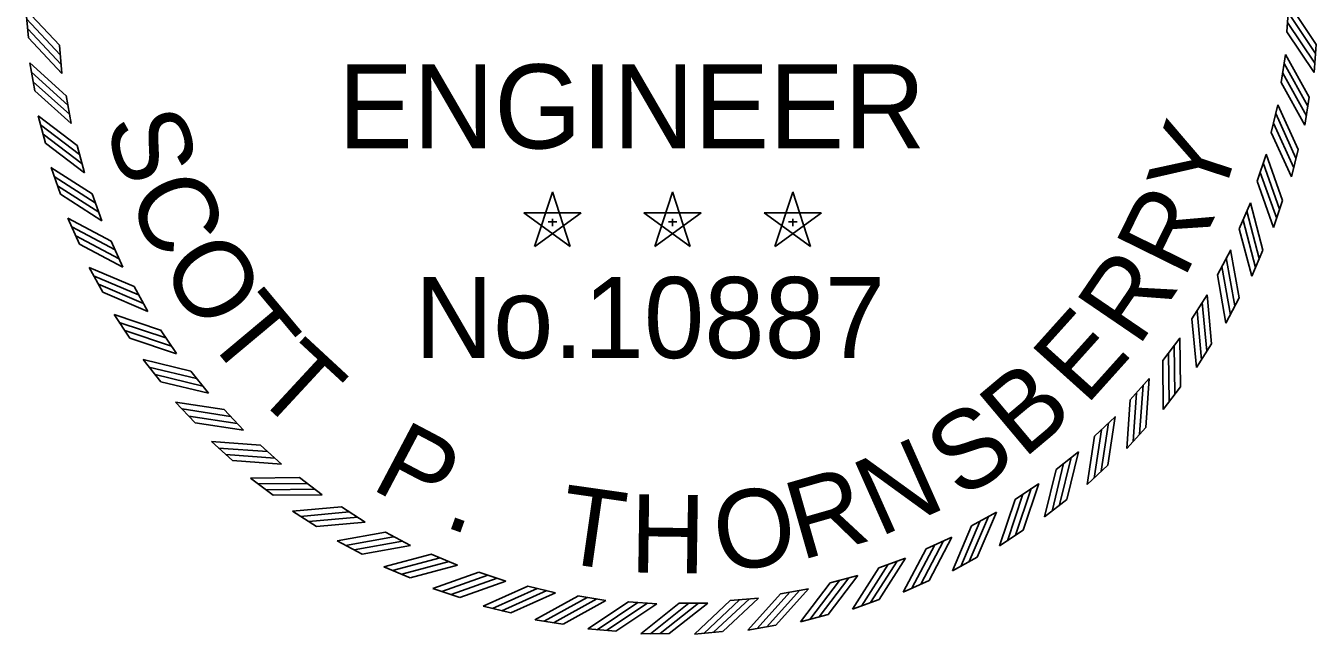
# Model space of a CAD drawing. Extents: x 3046 to 131673, y -8885 to 10756.
# Drawn here: x 3046.5 to 3294.3, y 323.2 to 440.1 of the extents above; entities that cross this region are included whole.
import ezdxf

# ---------------------------------------------------------------- set-up
doc = ezdxf.new("R2010")
doc.units = 0
doc.layers.add('STAMP_PP', color=7, linetype='Continuous')

msp = doc.modelspace()

# ---------------------------------------------------------------- linework, layer by layer
at = {"layer": 'STAMP_PP'}
for p, q in [((3289.08, 444.37), (3288.68, 438.93)), ((3046.98, 437.8), (3046.48, 443.22)), ((3053.43, 430.94), (3052.93, 436.37)), ((3294.31, 436.54), (3293.91, 431.11)), ((3288.42, 434.6), (3287.58, 429.21)), ((3048.2, 427.61), (3047.25, 432.97)), ((3055.19, 421.31), (3054.24, 426.68)), ((3292.99, 426.36), (3292.14, 420.99)), ((3286.96, 424.92), (3285.67, 419.62)), ((3050.25, 417.57), (3048.87, 422.83)), ((3057.74, 411.86), (3056.35, 417.13)), ((3284.71, 415.4), (3282.99, 410.22)), ((3290.83, 416.34), (3289.55, 411.05)), ((3053.13, 407.72), (3051.32, 412.85)), ((3061.06, 402.65), (3059.24, 407.79)), ((3147.61, 408.16), (3144.21, 397.72)), ((3151, 397.72), (3147.62, 408.17)), ((3170.69, 408.16), (3167.28, 397.72)), ((3174.08, 397.72), (3170.7, 408.17)), ((3193.77, 408.16), (3190.36, 397.72)), ((3197.16, 397.72), (3193.77, 408.17)), ((3287.86, 406.52), (3286.14, 401.36)), ((3153.1, 404.17), (3142.11, 404.19)), ((3142.12, 404.17), (3151, 397.71)), ((3144.22, 397.72), (3153.11, 404.17)), ((3176.18, 404.17), (3165.19, 404.19)), ((3165.2, 404.17), (3174.08, 397.71)), ((3167.3, 397.72), (3176.19, 404.17)), ((3199.25, 404.17), (3188.27, 404.19)), ((3188.28, 404.17), (3197.16, 397.71)), ((3190.37, 397.72), (3199.27, 404.17)), ((3281.68, 406.09), (3279.53, 401.08)), ((3056.81, 398.15), (3054.58, 403.11)), ((3146.83, 402.42), (3148.46, 402.42)), ((3147.62, 403.01), (3147.62, 401.63)), ((3169.91, 402.42), (3171.54, 402.42)), ((3170.7, 403.01), (3170.7, 401.63)), ((3192.98, 402.42), (3194.62, 402.42)), ((3193.78, 403.01), (3193.78, 401.63)), ((3065.13, 393.75), (3062.9, 398.72)), ((3277.89, 397.07), (3275.33, 392.25)), ((3284.08, 396.99), (3281.94, 391.99)), ((3061.27, 388.91), (3058.63, 393.67)), ((3069.93, 385.22), (3067.29, 389.99)), ((3273.36, 388.39), (3270.42, 383.8)), ((3279.53, 387.8), (3276.98, 382.99)), ((3066.47, 380.07), (3063.45, 384.6)), ((3075.41, 377.11), (3072.38, 381.65)), ((3268.14, 380.11), (3264.83, 375.78)), ((3274.23, 379.01), (3271.3, 374.43)), ((3072.39, 371.7), (3069.01, 375.96)), ((3081.54, 369.48), (3078.15, 373.75)), ((3262.25, 372.3), (3258.59, 368.25)), ((3268.23, 370.7), (3264.93, 366.37)), ((3078.98, 363.84), (3075.25, 367.81)), ((3088.28, 362.38), (3084.55, 366.36)), ((3255.73, 364.99), (3251.75, 361.26)), ((3261.56, 362.91), (3257.92, 358.87)), ((3086.19, 356.55), (3082.15, 360.2)), ((3095.58, 355.87), (3091.54, 359.52)), ((3248.63, 358.25), (3244.36, 354.86)), ((3254.27, 355.69), (3250.31, 351.97)), ((3093.98, 349.88), (3089.66, 353.18)), ((3103.4, 349.98), (3099.06, 353.29)), ((3241, 352.12), (3236.47, 349.1)), ((3111.67, 344.75), (3107.08, 347.69)), ((3246.41, 349.1), (3242.15, 345.72)), ((3102.3, 343.88), (3097.72, 346.81)), ((3232.9, 346.64), (3228.12, 344)), ((3120.35, 340.23), (3115.53, 342.78)), ((3238.04, 343.19), (3233.51, 340.17)), ((3111.08, 338.58), (3106.27, 341.13)), ((3224.36, 341.85), (3219.39, 339.61)), ((3129.38, 336.44), (3124.36, 338.58)), ((3215.46, 337.78), (3210.32, 335.96)), ((3229.2, 337.98), (3224.44, 335.35)), ((3120.27, 334.03), (3115.27, 336.17)), ((3138.68, 333.4), (3133.51, 335.13)), ((3148.21, 331.15), (3142.91, 332.44)), ((3206.25, 334.46), (3200.98, 333.07)), ((3219.96, 333.52), (3215, 331.29)), ((3129.81, 330.26), (3124.65, 331.97)), ((3157.88, 329.69), (3152.5, 330.54)), ((3187.18, 330.14), (3181.75, 329.64)), ((3196.8, 331.91), (3191.43, 330.96)), ((3210.39, 329.84), (3205.26, 328.03)), ((3139.62, 327.28), (3134.34, 328.57)), ((3167.65, 329.03), (3162.21, 329.43)), ((3177.44, 329.18), (3171.98, 329.13)), ((3149.65, 325.12), (3144.28, 325.97)), ((3190.5, 324.91), (3185.14, 323.97)), ((3200.55, 326.97), (3195.28, 325.58)), ((3159.82, 323.8), (3154.39, 324.2)), ((3170.07, 323.33), (3164.62, 323.28)), ((3180.31, 323.7), (3174.9, 323.2))]:
    msp.add_line(p, q, dxfattribs=at)
for points in [[(3289.08, 444.37), (3294.31, 436.54)], [(3052.93, 436.36), (3046.48, 443.22)], [(3053.08, 434.55), (3046.63, 441.41)], [(3288.93, 442.63), (3294.16, 434.8)], [(3053.29, 432.67), (3046.84, 439.54)], [(3288.68, 438.93), (3293.91, 431.1)], [(3288.83, 440.74), (3294.06, 432.91)], [(3053.43, 430.93), (3046.99, 437.79)], [(3288.42, 434.61), (3292.99, 426.37)], [(3054.24, 426.67), (3047.25, 432.98)], [(3288.13, 432.88), (3292.7, 424.65)], [(3054.54, 424.88), (3047.55, 431.19)], [(3054.91, 423.03), (3047.92, 429.33)], [(3287.58, 429.22), (3292.15, 420.98)], [(3287.88, 431.01), (3292.44, 422.77)], [(3055.2, 421.3), (3048.21, 427.61)], [(3286.96, 424.93), (3290.83, 416.35)], [(3056.35, 417.13), (3048.86, 422.83)], [(3286.12, 421.39), (3289.99, 412.8)], [(3286.53, 423.23), (3290.4, 414.65)], [(3056.8, 415.37), (3049.31, 421.07)], [(3057.32, 413.55), (3049.83, 419.26)], [(3285.68, 419.63), (3289.55, 411.05)], [(3057.75, 411.85), (3050.26, 417.56)], [(3284.71, 415.41), (3287.85, 406.53)], [(3059.24, 407.79), (3051.31, 412.85)], [(3283.58, 411.94), (3286.73, 403.07)], [(3284.14, 413.75), (3287.29, 404.88)], [(3059.83, 406.07), (3051.9, 411.14)], [(3060.5, 404.3), (3052.57, 409.37)], [(3282.99, 410.23), (3286.14, 401.36)], [(3061.07, 402.65), (3053.14, 407.72)], [(3280.97, 404.5), (3283.37, 395.39)], [(3281.67, 406.1), (3284.08, 397)], [(3062.9, 398.72), (3054.57, 403.11)], [(3280.27, 402.74), (3282.67, 393.64)], [(3063.62, 397.06), (3055.3, 401.45)], [(3064.44, 395.35), (3056.11, 399.75)], [(3279.54, 401.08), (3281.94, 391.98)], [(3065.14, 393.75), (3056.82, 398.14)], [(3277.88, 397.08), (3279.53, 387.81)], [(3277.05, 395.54), (3278.69, 386.27)], [(3067.29, 389.98), (3058.63, 393.67)], [(3068.15, 388.39), (3059.49, 392.08)], [(3275.34, 392.25), (3276.98, 382.98)], [(3276.2, 393.85), (3277.85, 384.58)], [(3069.1, 386.75), (3060.44, 390.45)], [(3069.93, 385.21), (3061.27, 388.91)], [(3272.4, 386.93), (3273.28, 377.56)], [(3273.36, 388.4), (3274.23, 379.02)], [(3072.38, 381.64), (3063.45, 384.6)], [(3271.42, 385.32), (3272.29, 375.94)], [(3073.37, 380.12), (3064.44, 383.09)], [(3270.43, 383.8), (3271.3, 374.43)], [(3074.46, 378.57), (3065.52, 381.54)], [(3075.41, 377.1), (3066.48, 380.07)], [(3268.14, 380.12), (3268.23, 370.71)], [(3265.95, 377.21), (3266.04, 367.8)], [(3267.06, 378.74), (3267.16, 369.33)], [(3078.15, 373.74), (3069, 375.96)], [(3079.26, 372.31), (3070.11, 374.53)], [(3264.83, 375.78), (3264.93, 366.37)], [(3080.47, 370.86), (3071.32, 373.08)], [(3262.25, 372.3), (3261.57, 362.91)], [(3081.55, 369.48), (3072.4, 371.69)], [(3259.82, 369.59), (3259.14, 360.2)], [(3261.06, 371.02), (3260.38, 361.63)], [(3084.55, 366.35), (3075.25, 367.81)], [(3258.6, 368.25), (3257.92, 358.86)], [(3085.78, 365.02), (3076.48, 366.47)], [(3087.1, 363.67), (3077.8, 365.12)], [(3255.73, 365), (3254.28, 355.7)], [(3088.29, 362.38), (3078.98, 363.84)], [(3253.09, 362.49), (3251.64, 353.19)], [(3254.44, 363.81), (3252.99, 354.51)], [(3091.54, 359.52), (3082.15, 360.2)], [(3251.76, 361.26), (3250.3, 351.96)], [(3092.87, 358.29), (3083.48, 358.97)], [(3094.3, 357.05), (3084.91, 357.73)], [(3247.25, 357.18), (3245.04, 348.04)], [(3248.64, 358.26), (3246.42, 349.11)], [(3095.59, 355.87), (3086.2, 356.55)], [(3244.37, 354.86), (3242.15, 345.72)], [(3245.8, 355.98), (3243.58, 346.83)], [(3099.07, 353.28), (3089.65, 353.18)], [(3100.5, 352.16), (3091.08, 352.07)], [(3241.01, 352.13), (3238.04, 343.19)], [(3102.02, 351.05), (3092.61, 350.96)], [(3103.41, 349.98), (3093.99, 349.88)], [(3237.99, 350.09), (3235.03, 341.15)], [(3239.54, 351.17), (3236.58, 342.24)], [(3107.08, 347.68), (3097.71, 346.81)], [(3236.47, 349.1), (3233.51, 340.16)], [(3108.6, 346.69), (3099.23, 345.82)], [(3110.22, 345.71), (3100.84, 344.84)], [(3111.68, 344.75), (3102.31, 343.88)], [(3229.72, 344.86), (3226.03, 336.2)], [(3231.36, 345.81), (3227.66, 337.16)], [(3232.9, 346.65), (3229.2, 337.99)], [(3115.54, 342.77), (3106.27, 341.13)], [(3228.13, 344), (3224.44, 335.34)], [(3117.13, 341.91), (3107.86, 340.27)], [(3118.82, 341.06), (3109.55, 339.42)], [(3120.36, 340.23), (3111.09, 338.58)], [(3219.39, 339.61), (3215, 331.29)], [(3221.05, 340.34), (3216.66, 332.01)], [(3222.76, 341.15), (3218.37, 332.83)], [(3224.36, 341.86), (3219.97, 333.53)], [(3124.37, 338.57), (3115.26, 336.17)], [(3126.03, 337.85), (3116.92, 335.44)], [(3127.78, 337.14), (3118.68, 334.74)], [(3213.81, 337.22), (3208.74, 329.28)], [(3215.46, 337.78), (3210.4, 329.85)], [(3129.38, 336.44), (3120.28, 334.03)], [(3133.51, 335.12), (3124.64, 331.97)], [(3210.33, 335.96), (3205.26, 328.02)], [(3212.04, 336.55), (3206.97, 328.61)], [(3135.23, 334.53), (3126.35, 331.38)], [(3137.03, 333.97), (3128.16, 330.83)], [(3138.69, 333.41), (3129.82, 330.26)], [(3142.91, 332.43), (3134.33, 328.56)], [(3200.99, 333.07), (3195.28, 325.58)], [(3202.74, 333.51), (3197.04, 326.02)], [(3204.56, 334.03), (3198.85, 326.54)], [(3206.26, 334.46), (3200.55, 326.97)], [(3144.67, 331.99), (3136.09, 328.12)], [(3146.52, 331.58), (3137.93, 327.71)], [(3148.21, 331.15), (3139.63, 327.28)], [(3152.5, 330.53), (3144.27, 325.97)], [(3154.29, 330.23), (3146.06, 325.67)], [(3156.16, 329.98), (3147.93, 325.42)], [(3157.89, 329.69), (3149.66, 325.13)], [(3181.75, 329.64), (3174.89, 323.19)], [(3183.56, 329.79), (3176.7, 323.34)], [(3185.44, 330.01), (3178.58, 323.56)], [(3187.18, 330.15), (3180.32, 323.7)], [(3191.44, 330.96), (3185.14, 323.96)], [(3193.23, 331.25), (3186.92, 324.26)], [(3195.08, 331.62), (3188.78, 324.63)], [(3196.81, 331.91), (3190.5, 324.92)], [(3162.22, 329.43), (3154.39, 324.2)], [(3164.02, 329.28), (3156.2, 324.05)], [(3165.91, 329.18), (3158.08, 323.95)], [(3167.66, 329.04), (3159.83, 323.81)], [(3171.99, 329.13), (3164.62, 323.27)], [(3173.8, 329.13), (3166.43, 323.27)], [(3175.69, 329.19), (3168.32, 323.33)], [(3177.44, 329.19), (3170.07, 323.33)]]:
    msp.add_lwpolyline(points, dxfattribs=at)

# ---------------------------------------------------------------- texts
for s, height, p in [('ENGINEER', 16.155, (3106.43, 416.53)), ('No.10887', 15.578, (3121.19, 376.25))]:
    msp.add_text(s, height=height, dxfattribs=at).set_placement(p)
for s, rotation, p in [('S', 286.9475, (3061.59, 421.47)), ('Y', 71.7733, (3275.78, 405.43)), ('C', 294.2435, (3065.77, 407.76)), ('R', 63.7477, (3268.9, 391.25)), ('O', 301.9044, (3071.99, 394.05)), ('R', 55.7221, (3260.1, 378.16)), ('T', 309.93, (3080.41, 380.72)), ('E', 48.0613, (3250.08, 366.93)), ('T', 317.226, (3089.62, 369.73)), ('B', 40.0357, (3238.07, 356.71)), ('S', 32.7397, (3226.01, 348.95)), ('P', 332.1828, (3112.43, 351.3)), ('N', 23.9845, (3210.39, 341.76)), ('R', 15.9589, (3195.26, 337.33)), ('T', 351.882, (3148.26, 337.1)), ('H', 359.178, (3162.46, 335.08)), ('O', 7.9332, (3179.65, 335.05)), ('.', 340.2084, (3126.42, 344.03))]:
    msp.add_text(s, height=15.03, rotation=rotation, dxfattribs=at).set_placement(p)

doc.saveas('drawing.dxf')
